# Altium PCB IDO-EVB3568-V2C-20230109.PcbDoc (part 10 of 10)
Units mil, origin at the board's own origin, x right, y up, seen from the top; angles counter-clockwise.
Board outline 5318 x 3544 mil, 2 copper layers (TOP, BOTTOM), stack 6.8 mil thick; 790 components, 626 nets, 2890 pads, 1922 vias.
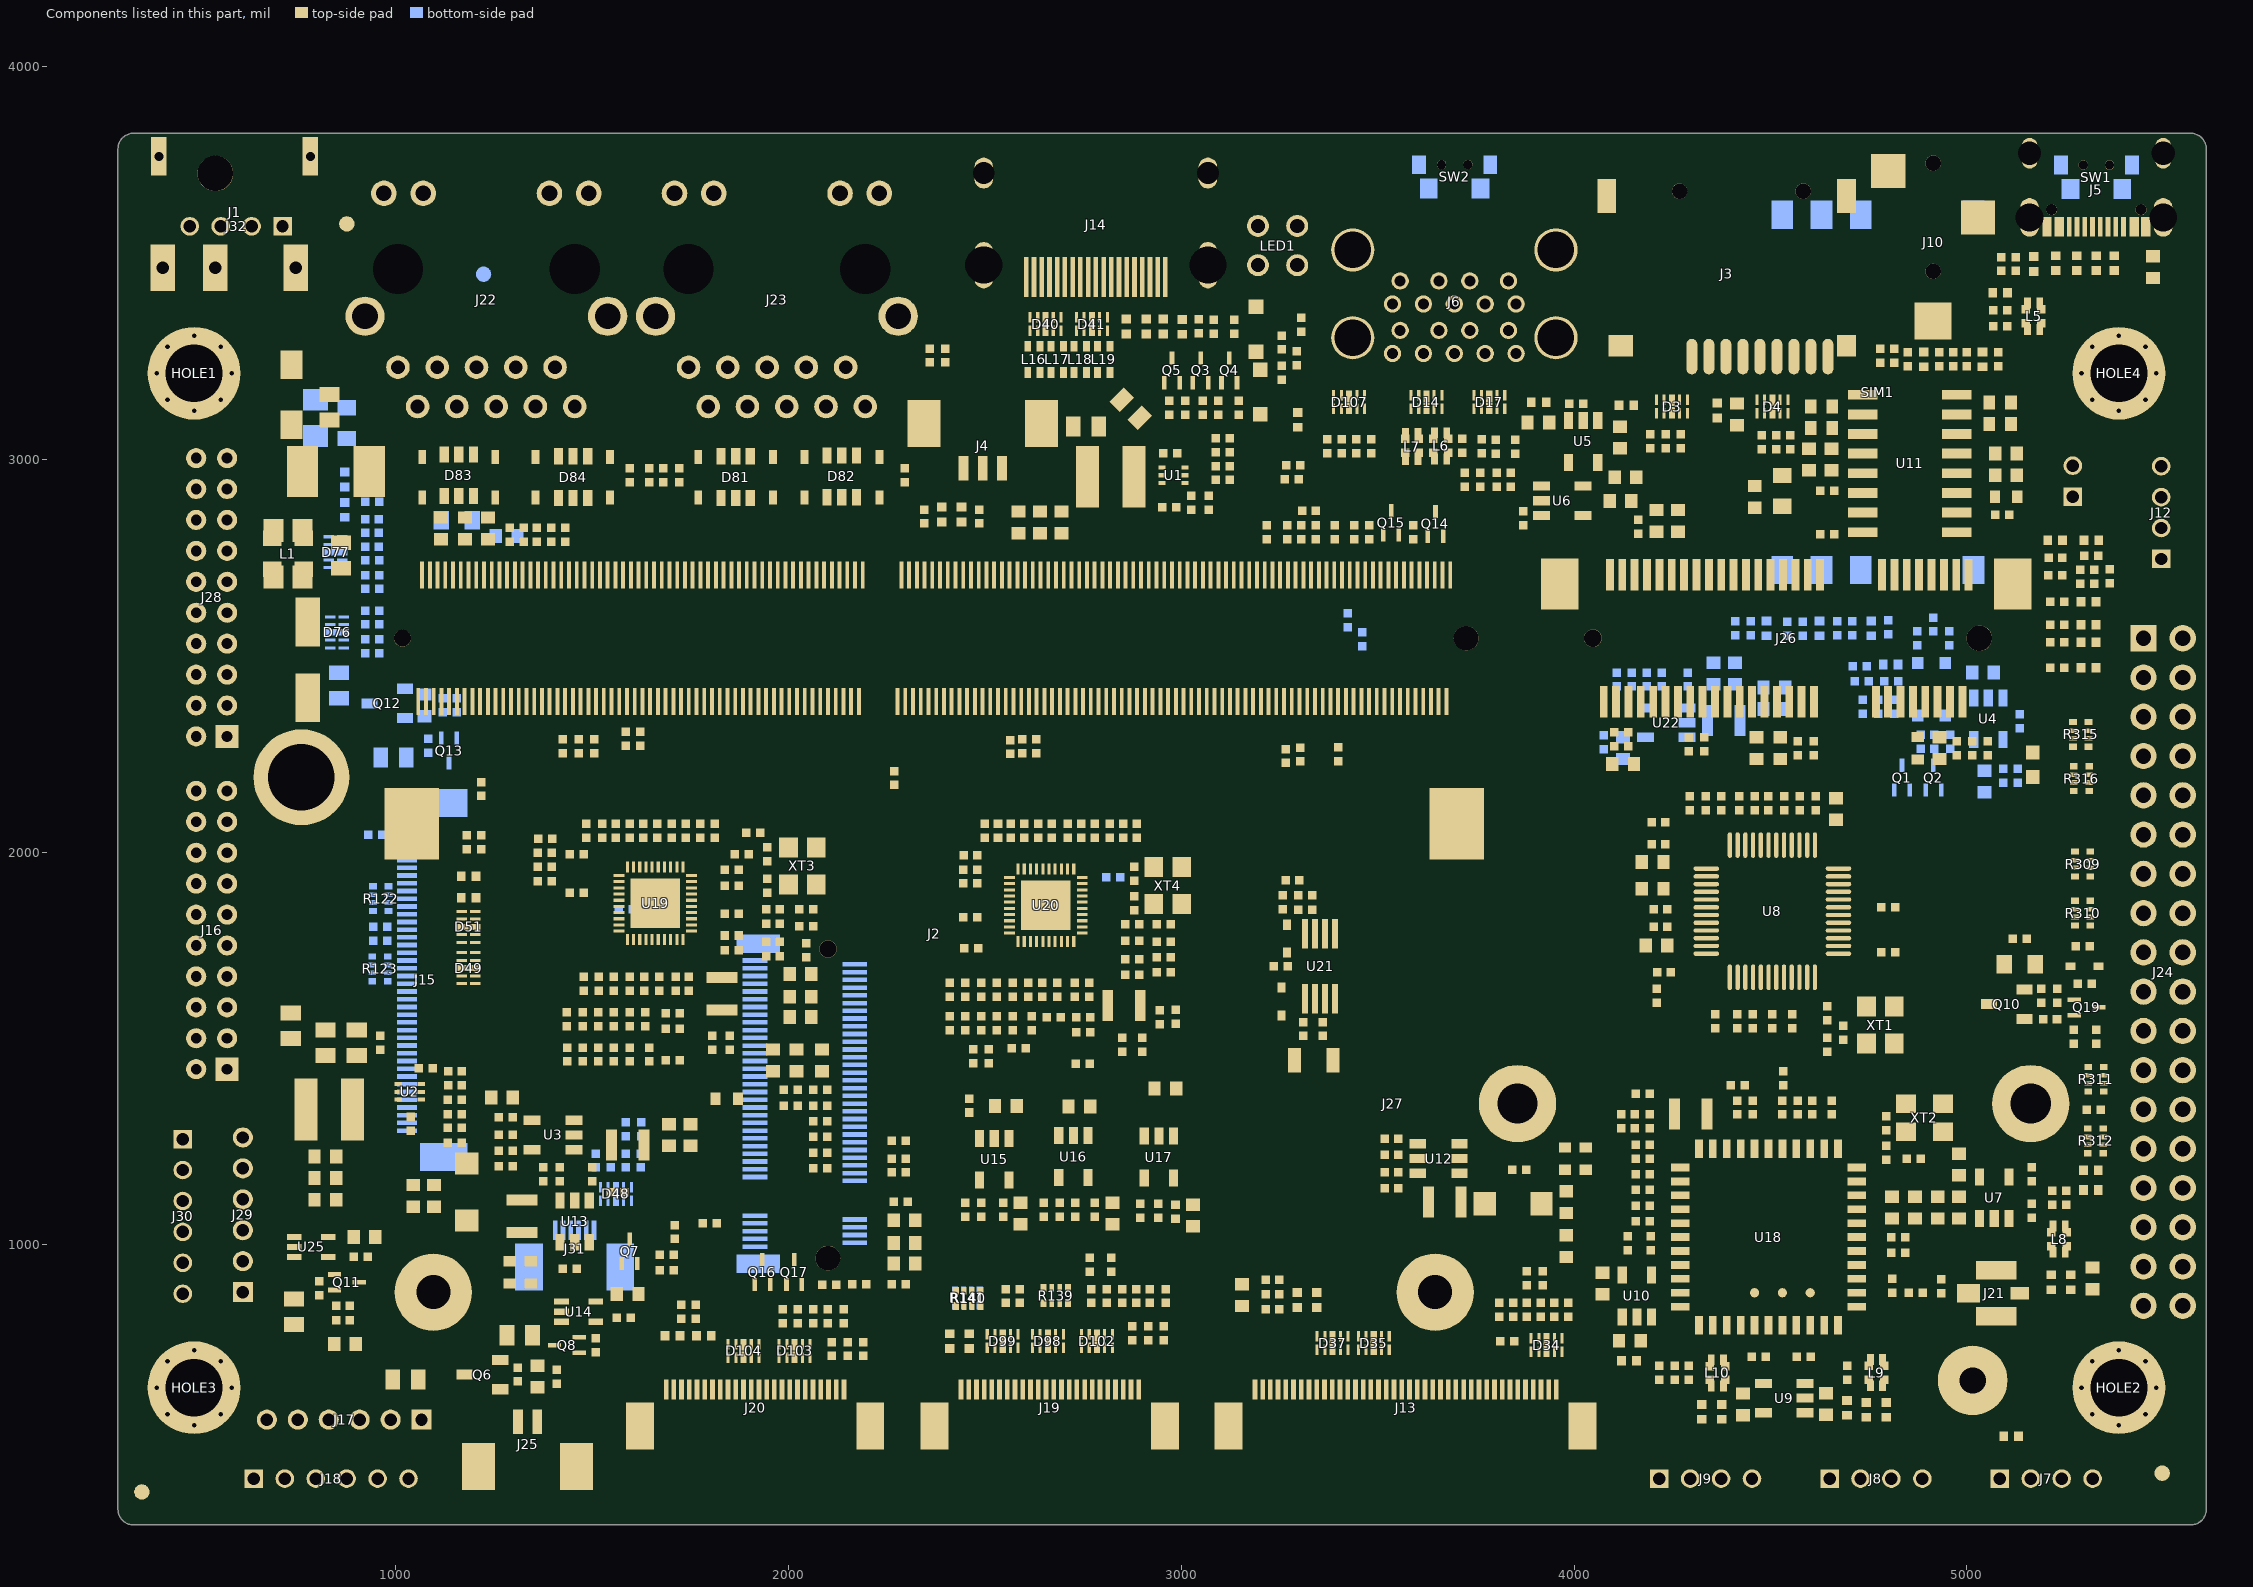
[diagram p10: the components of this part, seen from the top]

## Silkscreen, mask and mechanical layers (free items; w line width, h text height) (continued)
NCLEGEND-1-4:
  circle w1: c7267.5,2346.67 r20
  lines w1: 6818,-3366.9 11654,-3366.9 ; 6818,-3112.97 11654,-3112.97 ; 6818,-2859.03 11654,-2859.03 ; 6818,-2605.09 11654,-2605.09 ; 6818,-2351.16 11654,-2351.16 ; 6818,-2097.22 11654,-2097.22 ; 6818,-1843.29 11654,-1843.29 ; 6818,-1589.35 11654,-1589.35 ; 6818,-1335.41 11654,-1335.41 ; 6818,-1081.48 11654,-1081.48 ; 6818,-827.54 11654,-827.54 ; 6818,-573.6 11654,-573.6 ; 6818,-319.67 11654,-319.67 ; 6818,-65.73 11654,-65.73 ; 6818,188.21 11654,188.21 ; 6818,442.14 11654,442.14 ; 6818,696.08 11654,696.08 ; 6818,950.02 11654,950.02 ; 6818,1203.95 11654,1203.95 ; 6818,1457.89 11654,1457.89 ; 6818,1711.83 11654,1711.83 ; 6818,1965.76 11654,1965.76 ; 6818,2219.7 11654,2219.7 ; 6818,2473.64 11654,2473.64 ; 6818,2727.57 11654,2727.57 ; 6818,2981.51 11654,2981.51 ; 6818,3235.45 11654,3235.45 ; 6818,3489.38 11654,3489.38 ; 6818,3743.32 11654,3743.32 ; 6818,3997.25 11654,3997.25 ; 6818,4251.19 11654,4251.19 ; 6818,4505.13 11654,4505.13 ; 6818,4759.06 11654,4759.06 ; 6818,5013 11654,5013 ; 6818,5263 11654,5263 ; 6818,5513 11654,5513 ; 7263.56,4886.03 7271.44,4886.03 ; 7267.5,4882.1 7267.5,4889.97 ; 7717,-3620.84 7717,5263 ; 9608,-3620.84 9608,5263 ; 10879,-3620.84 10879,5263 ; 6818,-3620.84 6818,5763 11654,5763 11654,-3620.84 6818,-3620.84 ; 7228.13,-3255.69 7228.13,-3224.19 7306.87,-3224.19 7306.87,-3255.69 7228.13,-3255.69 ; 7228.13,-2997.81 7228.13,-2974.19 7306.87,-2974.19 7306.87,-2997.81 7228.13,-2997.81 ; 7233.41,3870.29 7243.39,3846.18 7267.5,3836.2 7291.61,3846.18 7301.59,3870.29 7291.61,3894.39 7267.5,3904.38 7243.39,3894.39 7233.41,3870.29 ; 7234.04,-3521.43 ccw(c7234.04,-3493.87) 7234.04,-3466.31 7300.96,-3466.31 ccw(c7300.96,-3493.87) 7300.96,-3521.43 7234.04,-3521.43 ; 7237.97,2595.68 ccw(c7267.5,2595.68) 7297.03,2595.68 7297.03,2605.52 ccw(c7267.5,2605.52) 7237.97,2605.52 7237.97,2595.68 ; 7243.88,-2755.68 ccw(c7243.88,-2732.06) 7243.88,-2708.44 7291.12,-2708.44 ccw(c7291.12,-2732.06) 7291.12,-2755.68 7243.88,-2755.68 ; 7247.81,2839.78 7247.81,2869.3 7287.19,2869.3 7287.19,2839.78 7247.81,2839.78 ; 7249.78,-2501.75 ccw(c7249.78,-2478.13) 7249.78,-2454.51 7285.22,-2454.51 ccw(c7285.22,-2478.13) 7285.22,-2501.75 7249.78,-2501.75 ; 7250,3344.91 7267.5,3379.91 7285,3344.91 7250,3344.91 ; 7251.75,3616.35 7267.5,3632.1 7283.25,3616.35 7267.5,3600.6 7251.75,3616.35 ; 7253.5,4117.22 7267.5,4110.22 7281.5,4117.22 7281.5,4131.22 7267.5,4138.22 7253.5,4131.22 7253.5,4117.22 ; 7253.72,-2251.75 ccw(c7253.72,-2224.19) 7253.72,-2196.63 7281.28,-2196.63 ccw(c7281.28,-2224.19) 7281.28,-2251.75 7253.72,-2251.75 ; 7253.72,4378.16 7260.61,4364.38 7274.39,4364.38 7281.28,4378.16 7274.39,4391.94 7260.61,4391.94 7253.72,4378.16 ; 7261.59,4626.19 7273.41,4626.19 7273.41,4638 7261.59,4638 7261.59,4626.19 ; 7263,3081.48 ccw(c7263,3108.48) 7263,3135.48 7272,3135.48 ccw(c7272,3108.48) 7272,3081.48 7263,3081.48
  text "DRILL CHART: TOP to BOTTOM" at 7936,5575.5 h125
  text "ALL UNITS ARE IN MILS" at 8186,5325.5 h125
  text "FIGURE" at 6967.5,5075.5 h125
  text "SIZE" at 8462.5,5075.5 h125
  text "PLATED" at 9943.5,5075.5 h125
  text "QTY" at 11116.5,5075.5 h125
  text "7.874" at 8412.5,4823.53 h125
  text "PLATED" at 9943.5,4823.53 h125
  text "44" at 11166.5,4823.53 h125
  text "11.811" at 8362.5,4569.6 h125
  text "PLATED" at 9943.5,4569.6 h125
  text "1914" at 11066.5,4569.6 h125
  text "27.559" at 8362.5,4315.66 h125
  text "PLATED" at 9943.5,4315.66 h125
  text "40" at 11166.5,4315.66 h125
  text "28.0" at 8462.5,4061.72 h125
  text "PLATED" at 9943.5,4061.72 h125
  text "18" at 11166.5,4061.72 h125
  text "31.496" at 8362.5,3807.79 h125
  text "PLATED" at 9943.5,3807.79 h125
  text "12" at 11166.5,3807.79 h125
  text "31.496" at 8362.5,3553.85 h125
  text "PLATED" at 9943.5,3553.85 h125
  text "34" at 11166.5,3553.85 h125
  text "35.0" at 8462.5,3299.91 h125
  text "PLATED" at 9943.5,3299.91 h125
  text "20" at 11166.5,3299.91 h125
  text "36.0" at 8462.5,3045.98 h125
  text "PLATED" at 9943.5,3045.98 h125
  text "4" at 11216.5,3045.98 h125
  text "39.37" at 8412.5,2792.04 h125
  text "PLATED" at 9943.5,2792.04 h125
  text "36" at 11166.5,2792.04 h125
  text "39.37" at 8412.5,2538.1 h125
  text "PLATED" at 9943.5,2538.1 h125
  text "4" at 11216.5,2538.1 h125
  text "40.0" at 8462.5,2284.17 h125
  text "PLATED" at 9943.5,2284.17 h125
  text "8" at 11216.5,2284.17 h125
  text "65.0" at 8462.5,2030.23 h125
  text "PLATED" at 9943.5,2030.23 h125
  text "4" at 11216.5,2030.23 h125
  text "66.929" at 8362.5,1776.29 h125
  text "PLATED" at 9943.5,1776.29 h125
  text "1" at 11216.5,1776.29 h125
  text "86.614" at 8362.5,1522.36 h125
  text "PLATED" at 9943.5,1522.36 h125
  text "2" at 11216.5,1522.36 h125
  text "93.0" at 8462.5,1268.42 h125
  text "PLATED" at 9943.5,1268.42 h125
  text "4" at 11216.5,1268.42 h125
  text "102.362" at 8312.5,1014.48 h125
  text "PLATED" at 9943.5,1014.48 h125
  text "2" at 11216.5,1014.48 h125
  text "145.669" at 8312.5,760.55 h125
  text "PLATED" at 9943.5,760.55 h125
  text "4" at 11216.5,760.55 h125
  text "169.291" at 8312.5,506.61 h125
  text "PLATED" at 9943.5,506.61 h125
  text "1" at 11216.5,506.61 h125
  text "23.622" at 8362.5,252.68 h125
  text "NON-PLATED" at 9743.5,252.68 h125
  text "4" at 11216.5,252.68 h125
  text "27.992" at 8362.5,-1.26 h125
  text "NON-PLATED" at 9743.5,-1.26 h125
  text "2" at 11216.5,-1.26 h125
  text "43.311" at 8362.5,-255.2 h125
  text "NON-PLATED" at 9743.5,-255.2 h125
  text "1" at 11216.5,-255.2 h125
  text "44.016" at 8362.5,-509.13 h125
  text "NON-PLATED" at 9743.5,-509.13 h125
  text "1" at 11216.5,-509.13 h125
  text "45.0" at 8462.5,-763.07 h125
  text "NON-PLATED" at 9743.5,-763.07 h125
  text "1" at 11216.5,-763.07 h125
  text "62.988" at 8362.5,-1017.01 h125
  text "NON-PLATED" at 9743.5,-1017.01 h125
  text "1" at 11216.5,-1017.01 h125
  text "62.992" at 8362.5,-1270.94 h125
  text "NON-PLATED" at 9743.5,-1270.94 h125
  text "1" at 11216.5,-1270.94 h125
  text "65.0" at 8462.5,-1524.88 h125
  text "NON-PLATED" at 9743.5,-1524.88 h125
  text "1" at 11216.5,-1524.88 h125
  text "90.551" at 8362.5,-1778.82 h125
  text "NON-PLATED" at 9743.5,-1778.82 h125
  text "1" at 11216.5,-1778.82 h125
  text "128.0" at 8412.5,-2032.75 h125
  text "NON-PLATED" at 9743.5,-2032.75 h125
  text "4" at 11216.5,-2032.75 h125
  text "55.118x27.559" at 8012.5,-2286.69 h125
  text "PLATED" at 9943.5,-2286.69 h125
  text "2" at 11216.5,-2286.69 h125
  text "59.055x23.622" at 8012.5,-2540.63 h125
  text "PLATED" at 9943.5,-2540.63 h125
  text "2" at 11216.5,-2540.63 h125
  text "70.866x23.622" at 8012.5,-2794.56 h125
  text "PLATED" at 9943.5,-2794.56 h125
  text "2" at 11216.5,-2794.56 h125
  text "78.74x23.622" at 8062.5,-3048.5 h125
  text "PLATED" at 9943.5,-3048.5 h125
  text "2" at 11216.5,-3048.5 h125
  text "78.74x31.5" at 8162.5,-3302.44 h125
  text "PLATED" at 9943.5,-3302.44 h125
  text "3" at 11216.5,-3302.44 h125
  text "94.488x27.559" at 8012.5,-3556.37 h125
  text "PLATED" at 9943.5,-3556.37 h125
  text "2" at 11216.5,-3556.37 h125
DRAWING_ORIGIN:
  lines w1: -25,0 25,0 ; 0,-25 0,25
Mechanical 255:
  lines w1: 325,395 325,550 445,670 625,670 660,635 660,425 570,335 385,335 325,395 ; 490,3485 490,3640 610,3760 790,3760 825,3725 825,3515 735,3425 550,3425 490,3485 ; 630,2105 630,2260 750,2380 930,2380 965,2345 965,2135 875,2045 690,2045 630,2105 ; 665,2960 665,3115 785,3235 965,3235 1000,3200 1000,2990 910,2900 725,2900 665,2960 ; 1065,2345 1065,2395 1115,2395 1115,2345 1065,2345 ; 1555,1960 1555,2025 1565,2035 1745,2035 1750,2030 1750,1975 1725,1950 1565,1950 1555,1960 ; 1695,2090 1695,2150 1700,2155 1735,2155 1745,2145 1745,2090 1740,2085 1700,2085 1695,2090 ; 1745,2680 1745,2740 1750,2745 1785,2745 1795,2735 1795,2680 1790,2675 1750,2675 1745,2680 ; 2585,1960 2585,2025 2595,2035 2755,2035 2815,2035 2830,2020 2830,1980 2815,1965 2770,1965 2755,1950 2595,1950 2585,1960 ; 3155,3575 3155,3625 3205,3625 3205,3575 3155,3575 ; 3450,3519 3450,3674 3450,3689 3460,3699 3960,3699 3980,3679 3980,3519 3960,3499 3735,3499 3470,3499 3450,3519 ; 3455,2340 3455,2400 3460,2405 3495,2405 3505,2395 3505,2340 3500,2335 3460,2335 3455,2340 ; 4375,3575 4375,3730 4495,3850 4675,3850 4710,3815 4710,3605 4620,3515 4435,3515 4375,3575 ; 4425,2000 4425,2065 4435,2075 4595,2075 4610,2060 4610,2005 4595,1990 4435,1990 4425,2000 ; 4650,1740 4660,1730 4725,1730 4735,1740 4735,1900 4720,1915 4665,1915 4650,1900 4650,1740 ; 5010,3625 5010,3780 5010,3795 5020,3805 5520,3805 5540,3785 5540,3625 5520,3605 5295,3605 5030,3605 5010,3625 ; 5215,400 5215,555 5335,675 5515,675 5550,640 5550,430 5460,340 5275,340 5215,400 ; 5340,3570 5340,3620 5390,3620 5390,3570 5340,3570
